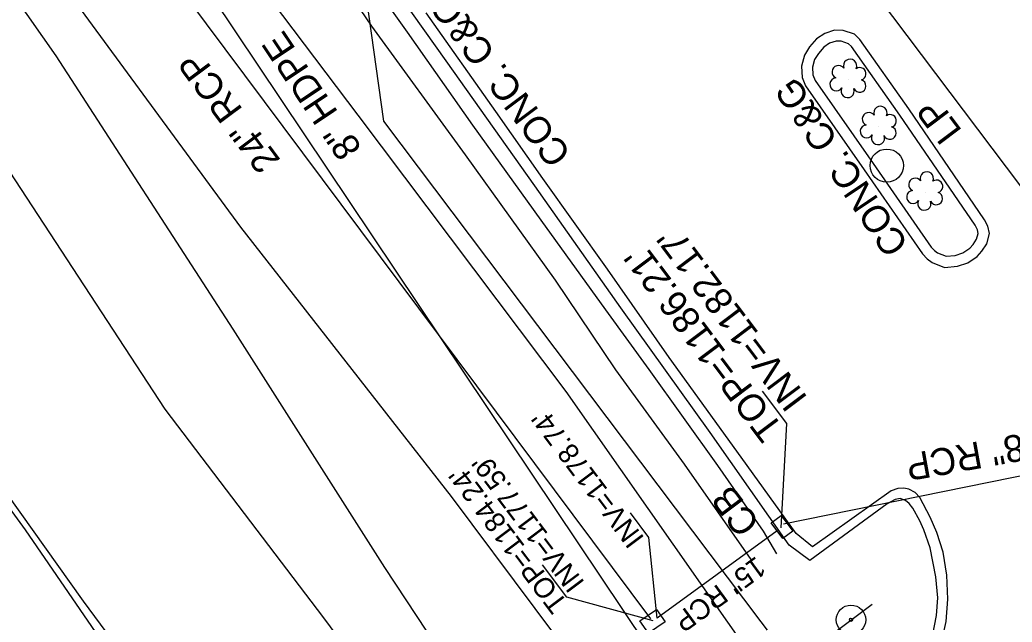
# Model space of a CAD drawing. Extents: x 1262092 to 1264624, y 774970 to 778314.
# Drawn here: x 1263536.5 to 1263683.6, y 776426.4 to 776515.7 of the extents above; entities that cross this region are included whole.
import ezdxf

# ---------------------------------------------------------------- set-up
doc = ezdxf.new("R2010")
doc.units = 0
for name, color, linetype in [('COGO Default Parcel', 7, 'Continuous'), ('Exist Horizontal Alignment Station Label', 7, 'Continuous'), ('Exist Horizontal Alignment Tick Large', 7, 'Continuous'), ('Exist Right of Way Line', 7, 'Continuous'), ('Exist Roads Curbs', 7, 'Continuous'), ('Exist Roads EOP', 7, 'Continuous'), ('Exist Roads EOP Other', 7, 'Continuous'), ('Exist Roads EOT', 7, 'Continuous'), ('Exist Structure Minor Catch Basin', 7, 'Continuous'), ('Exist Structure Minor Catch Basin Leader', 7, 'Continuous'), ('Exist Structure Minor Catch Basin Text', 7, 'Continuous'), ('Exist Structure Minor Catch Basin Top Elevation', 7, 'Continuous'), ('Exist Structure Minor Drop Inlet', 7, 'Continuous'), ('Exist Structure Minor Drop Inlet Leader', 7, 'Continuous'), ('Exist Structure Minor Drop Inlet Top Elevation', 7, 'Continuous'), ('Exist Structure Minor Pipes RCP 15 Inch', 7, 'Continuous'), ('Exist Structure Minor Pipes RCP 15 Inch Text', 7, 'Continuous'), ('Exist Structure Minor Pipes RCP 18 Inch', 7, 'Continuous'), ('Exist Structure Minor Pipes RCP 18 Inch Invert', 7, 'Continuous'), ('Exist Structure Minor Pipes RCP 18 Inch Leader', 7, 'Continuous'), ('Exist Structure Minor Pipes RCP 18 Inch Text', 7, 'Continuous'), ('Exist Structure Minor Pipes RCP 24 Inch', 7, 'Continuous'), ('Exist Structure Minor Pipes RCP 24 Inch Invert', 7, 'Continuous'), ('Exist Structure Minor Pipes RCP 24 Inch Text', 7, 'Continuous'), ('Exist Utilities Gas UG Line SUE LOS B', 7, 'Continuous'), ('Exist Utilities Other Pole Text', 7, 'Continuous'), ('Exist Utilities Sanitary Sewer UG Line', 7, 'Continuous'), ('Exist Utilities Sanitary Sewer UG Line Text', 7, 'Continuous'), ('Exist Utilities TV UG Cable SUE LOS B', 7, 'Continuous'), ('Exist Utilities Water UG Line SUE LOS B', 7, 'Continuous'), ('Sheet Clip Boundary CELL', 7, 'Continuous'), ('Sheet Plot Border Outside CELL', 7, 'Continuous')]:
    doc.layers.add(name, color=color, linetype=linetype)

msp = doc.modelspace()

# ---------------------------------------------------------------- linework, layer by layer
at = {"layer": 'COGO Default Parcel'}
msp.add_line((1263602.12, 776600.93), (1264624.2, 775243.33), dxfattribs=at)
at = {"layer": 'Exist Horizontal Alignment Station Label'}
msp.add_line((1263656.73, 776424.51), (1263662.83, 776429.11), dxfattribs=at)
for radius in [2.18, 0.24]:
    msp.add_circle((1263659.7, 776426.79), radius, dxfattribs=at)
at = {"layer": 'Exist Horizontal Alignment Tick Large'}
for p, q in [((1263659.33, 776506.88), (1263659.33, 776506.88)), ((1263663.83, 776499.9), (1263663.83, 776499.9)), ((1263670.7, 776490.19), (1263670.7, 776490.19))]:
    msp.add_line(p, q, dxfattribs=at)
for centre, radius, start, end in [((1263659.56, 776508.92), 0.99, 334.8391, 200.4717), ((1263657.85, 776508.01), 0.968, 35.8908, 245.4216), ((1263661, 776507.75), 0.929, 284.4567, 126.0861), ((1263657.53, 776506.17), 0.955, 95.1099, 327.9534), ((1263659.2, 776505.19), 0.984, 151.2797, 21.387), ((1263660.97, 776505.95), 0.937, 204.9913, 73.4601), ((1263664.06, 776501.94), 0.99, 334.8391, 200.4717), ((1263662.34, 776501.03), 0.968, 35.8908, 245.4216), ((1263665.5, 776500.77), 0.929, 284.4567, 126.0861), ((1263662.03, 776499.2), 0.955, 95.1099, 327.9534), ((1263665.46, 776498.97), 0.937, 204.9913, 73.4601), ((1263663.7, 776498.22), 0.984, 151.2797, 21.387), ((1263669.22, 776491.31), 0.968, 35.8908, 245.4216), ((1263670.93, 776492.23), 0.99, 334.8391, 200.4717), ((1263672.37, 776491.05), 0.929, 284.4567, 126.0861), ((1263668.9, 776489.48), 0.955, 95.1099, 327.9534), ((1263672.34, 776489.26), 0.937, 204.9913, 73.4601), ((1263670.57, 776488.5), 0.984, 151.2797, 21.387)]:
    msp.add_arc(centre, radius, start, end, dxfattribs=at)
at = {"layer": 'Exist Right of Way Line'}
for p, q in [((1263568.46, 776657.05), (1263590.4, 776500.74)), ((1263590.4, 776500.74), (1264585.76, 775179.25))]:
    msp.add_line(p, q, dxfattribs=at)
at = {"layer": 'Exist Roads Curbs'}
msp.add_lwpolyline([(1263671.81, 776424.58), (1263672.36, 776427.41), (1263672.56, 776430.06), (1263672.29, 776433.17), (1263671.44, 776437.47), (1263670.49, 776440.12), (1263669.89, 776441.48), (1263668.87, 776443.33), (1263668.3, 776444.05), (1263667.78, 776444.45), (1263666.99, 776444.75), (1263666.23, 776444.63), (1263665.05, 776443.98), (1263653.59, 776435.59), (1263650.54, 776437.87), (1263638.81, 776454.57), (1263625.58, 776473.06), (1263612.83, 776491.15), (1263599.68, 776509.65), (1263584.99, 776530.41)], dxfattribs=at)
msp.add_lwpolyline([(1263671.59, 776482.06), (1263672.07, 776481.53), (1263672.53, 776481.21), (1263673.79, 776480.69), (1263675.15, 776480.82), (1263676.3, 776481.18), (1263677.31, 776481.89), (1263677.83, 776482.44), (1263678.32, 776483.2), (1263678.55, 776484.08), (1263678.43, 776484.6), (1263678.1, 776485.29), (1263666.95, 776501.62), (1263659.79, 776511.78), (1263659.35, 776512.2), (1263658.24, 776512.57), (1263657.48, 776512.58), (1263656.53, 776512.27), (1263655.68, 776511.69), (1263654.86, 776510.77), (1263654.29, 776509.87), (1263653.99, 776508.72), (1263654.05, 776507.58), (1263654.41, 776506.74), (1263662.97, 776494.44)], close=True, dxfattribs=at)
at = {"layer": 'Exist Roads EOP'}
msp.add_lwpolyline([(1263574.23, 776391.25), (1263545.92, 776429.53), (1263517.71, 776469.12), (1263490.16, 776508.51), (1263476.85, 776530.74)], dxfattribs=at)
at = {"layer": 'Exist Roads EOP Other'}
msp.add_lwpolyline([(1263673.31, 776424.28), (1263673.81, 776426.51), (1263674.05, 776429.86), (1263673.91, 776433.39), (1263673.35, 776436.79), (1263672.43, 776439.72), (1263671.43, 776442.01), (1263669.88, 776444.92), (1263669.22, 776445.65), (1263668.25, 776446.14), (1263667.53, 776446.3), (1263666.66, 776446.27), (1263665.65, 776445.88), (1263653.99, 776437.59), (1263651.55, 776439.59), (1263642.76, 776451.81), (1263632.73, 776465.7), (1263623.6, 776478.76), (1263614.02, 776492.22), (1263607.07, 776502.16), (1263596.74, 776516.8)], dxfattribs=at)
msp.add_lwpolyline([(1263670.32, 776481.05), (1263670.99, 776480.31), (1263671.75, 776479.78), (1263673.55, 776479.04), (1263675.47, 776479.22), (1263677.02, 776479.71), (1263678.38, 776480.66), (1263679.11, 776481.44), (1263679.82, 776482.54), (1263680.22, 776484.06), (1263679.97, 776485.15), (1263679.51, 776486.1), (1263668.29, 776502.54), (1263661.03, 776512.84), (1263660.21, 776513.62), (1263658.52, 776514.18), (1263657.24, 776514.21), (1263655.8, 776513.74), (1263654.6, 776512.91), (1263653.56, 776511.75), (1263652.79, 776510.52), (1263652.36, 776508.89), (1263652.45, 776507.21), (1263652.98, 776505.95), (1263661.64, 776493.52)], close=True, dxfattribs=at)
at = {"layer": 'Exist Roads EOT'}
msp.add_lwpolyline([(1263482.8, 776515.47), (1263509.89, 776477.8), (1263537.29, 776440.12), (1263563.31, 776402.14), (1263589.36, 776362.47), (1263614.5, 776324.1), (1263634.59, 776293.28)], dxfattribs=at)
at = {"layer": 'Exist Structure Minor Catch Basin'}
msp.add_lwpolyline([(1263647.86, 776441.14), (1263649.33, 776442.24), (1263651.06, 776439.92), (1263649.59, 776438.82), (1263647.86, 776441.14)], dxfattribs=at)
at = {"layer": 'Exist Structure Minor Catch Basin Leader'}
msp.add_lwpolyline([(1263649.35, 776440.44), (1263650.17, 776455.91), (1263646.56, 776460.7)], dxfattribs=at)
at = {"layer": 'Exist Structure Minor Drop Inlet'}
msp.add_lwpolyline([(1263630.85, 776428.33), (1263632.13, 776426.47), (1263629.69, 776424.78), (1263628.41, 776426.64), (1263630.85, 776428.33)], dxfattribs=at)
at = {"layer": 'Exist Structure Minor Drop Inlet Leader'}
msp.add_lwpolyline([(1263630.4, 776426.61), (1263617.6, 776430.12), (1263613.99, 776434.91)], dxfattribs=at)
at = {"layer": 'Exist Structure Minor Pipes RCP 15 Inch'}
msp.add_line((1263648.77, 776439.99), (1263630.98, 776427), dxfattribs=at)
at = {"layer": 'Exist Structure Minor Pipes RCP 18 Inch'}
msp.add_line((1263649.71, 776441.03), (1263708.74, 776453), dxfattribs=at)
at = {"layer": 'Exist Structure Minor Pipes RCP 18 Inch Leader'}
msp.add_lwpolyline([(1263630.98, 776427), (1263629.75, 776438.99), (1263627, 776442.64)], dxfattribs=at)
at = {"layer": 'Exist Structure Minor Pipes RCP 24 Inch'}
msp.add_line((1263502.05, 776598.37), (1263629.98, 776426.93), dxfattribs=at)
at = {"layer": 'Exist Utilities Gas UG Line SUE LOS B'}
msp.add_lwpolyline([(1263999.19, 775839.39), (1263985.7, 775869), (1263961.35, 775898.49), (1263933.55, 775929.39), (1263903.92, 775964.01), (1263874.9, 776001.17), (1263844.84, 776038.67), (1263814.72, 776080.57), (1263786.93, 776117.1), (1263768.77, 776141.15), (1263740.07, 776178.28), (1263709.03, 776220.12), (1263678.63, 776261.22), (1263654.09, 776299.54), (1263639.97, 776350.31), (1263613.73, 776383.62), (1263581.55, 776427.09), (1263558.06, 776458.02), (1263528.1, 776503.73), (1263523.32, 776512.13)], dxfattribs=at)
msp.add_circle((1263665, 776494.13), 2.46, dxfattribs=at)
at = {"layer": 'Exist Utilities Sanitary Sewer UG Line'}
msp.add_line((1263677.43, 776351.4), (1263523.17, 776581.72), dxfattribs=at)
at = {"layer": 'Exist Utilities TV UG Cable SUE LOS B'}
msp.add_lwpolyline([(1263669.01, 776365.83), (1263671.56, 776379.52), (1263645.49, 776420.66), (1263617.5, 776460.63), (1263586.67, 776501.62), (1263562.63, 776533.45), (1263537.82, 776574.01)], dxfattribs=at)
at = {"layer": 'Exist Utilities Water UG Line SUE LOS B'}
for points in [[(1263769.27, 776215.45), (1263763.84, 776222.23), (1263735.1, 776261.82), (1263710.78, 776293), (1263676.58, 776339.78), (1263655.95, 776370.3), (1263625.27, 776411.83), (1263600.5, 776445.06), (1263569.27, 776485), (1263544.4, 776518.91), (1263522.5, 776549.75)], [(1263947.84, 775937.63), (1263921.48, 775975.65), (1263891.78, 776015.72), (1263866.35, 776051.64), (1263834.78, 776093.68), (1263806.91, 776131.82), (1263785.84, 776159.4), (1263762.42, 776192.1), (1263728.85, 776233.86), (1263701.99, 776270.27), (1263670.29, 776315.62), (1263645.61, 776350.98), (1263620.38, 776389.35), (1263590.58, 776434.56), (1263568.12, 776469.9), (1263541.87, 776510.41), (1263521.01, 776540.13)]]:
    msp.add_lwpolyline(points, dxfattribs=at)
at = {"layer": 'Sheet Clip Boundary CELL'}
for points in [[(1263546.93, 776574.52), (1263547.19, 776578.58), (1263548.24, 776578.65), (1263551.46, 776573.64), (1263563, 776557.07), (1263578.69, 776535.25), (1263593.93, 776513.92), (1263603.6, 776500.12), (1263613.72, 776486.02), (1263623.32, 776472.73), (1263629.72, 776463.9), (1263639.92, 776449.68), (1263646.7, 776439.91), (1263648.66, 776436.55)], [(1263644.88, 776435.7), (1263635.03, 776449.86), (1263624.82, 776463.85), (1263615.91, 776477.16), (1263602.54, 776495.72), (1263588.69, 776514.81), (1263578.03, 776530.49), (1263566.91, 776546.14)]]:
    msp.add_lwpolyline(points, dxfattribs=at)

# ---------------------------------------------------------------- texts
at = {"layer": 'Exist Structure Minor Catch Basin Text'}
msp.add_text('CB', height=4, rotation=126.9874, dxfattribs=at).set_placement((1263646.35, 776441.09))
at = {"layer": 'Exist Structure Minor Catch Basin Top Elevation'}
msp.add_text("TOP=1186.21'", height=4, rotation=126.9874, dxfattribs=at).set_placement((1263649.79, 776455.2))
at = {"layer": 'Exist Structure Minor Drop Inlet Top Elevation'}
msp.add_text("TOP=1184.24'", height=3, rotation=126.9874, dxfattribs=at).set_placement((1263617.84, 776429.23))
at = {"layer": 'Exist Structure Minor Pipes RCP 15 Inch Text'}
msp.add_text('15" RCP', height=3, rotation=216.1265, dxfattribs=at).set_placement((1263645.65, 776436.31))
at = {"layer": 'Exist Structure Minor Pipes RCP 18 Inch Invert'}
for s, height, p in [("INV=1182.17'", 4, (1263653.38, 776459.67)), ("INV=1178.74'", 3, (1263629.17, 776438.89))]:
    msp.add_text(s, height=height, rotation=126.9874, dxfattribs=at).set_placement(p)
at = {"layer": 'Exist Structure Minor Pipes RCP 18 Inch Text'}
msp.add_text('18" RCP', height=4, rotation=190.2504, dxfattribs=at).set_placement((1263687.88, 776454.94))
at = {"layer": 'Exist Structure Minor Pipes RCP 24 Inch Invert'}
msp.add_text("INV=1177.59'", height=3, rotation=126.9874, dxfattribs=at).set_placement((1263620.32, 776432.3))
at = {"layer": 'Exist Structure Minor Pipes RCP 24 Inch Text'}
msp.add_text('24" RCP', height=4, rotation=126.7305, dxfattribs=at).set_placement((1263575.24, 776494.94))
at = {"layer": 'Exist Utilities Other Pole Text'}
msp.add_text('LP', height=4, rotation=126.9746, dxfattribs=at).set_placement((1263676.27, 776499.28))
at = {"layer": 'Exist Utilities Sanitary Sewer UG Line Text'}
msp.add_text('8" HDPE', height=4, rotation=123.8148, dxfattribs=at).set_placement((1263587.31, 776496.73))
at = {"layer": 'Sheet Plot Border Outside CELL'}
for rotation, p in [(126.8505, (1263618.37, 776495.87)), (123.9489, (1263668.37, 776482.41))]:
    msp.add_text('CONC. C&G', height=4, rotation=rotation, dxfattribs=at).set_placement(p)

doc.saveas('drawing.dxf')
